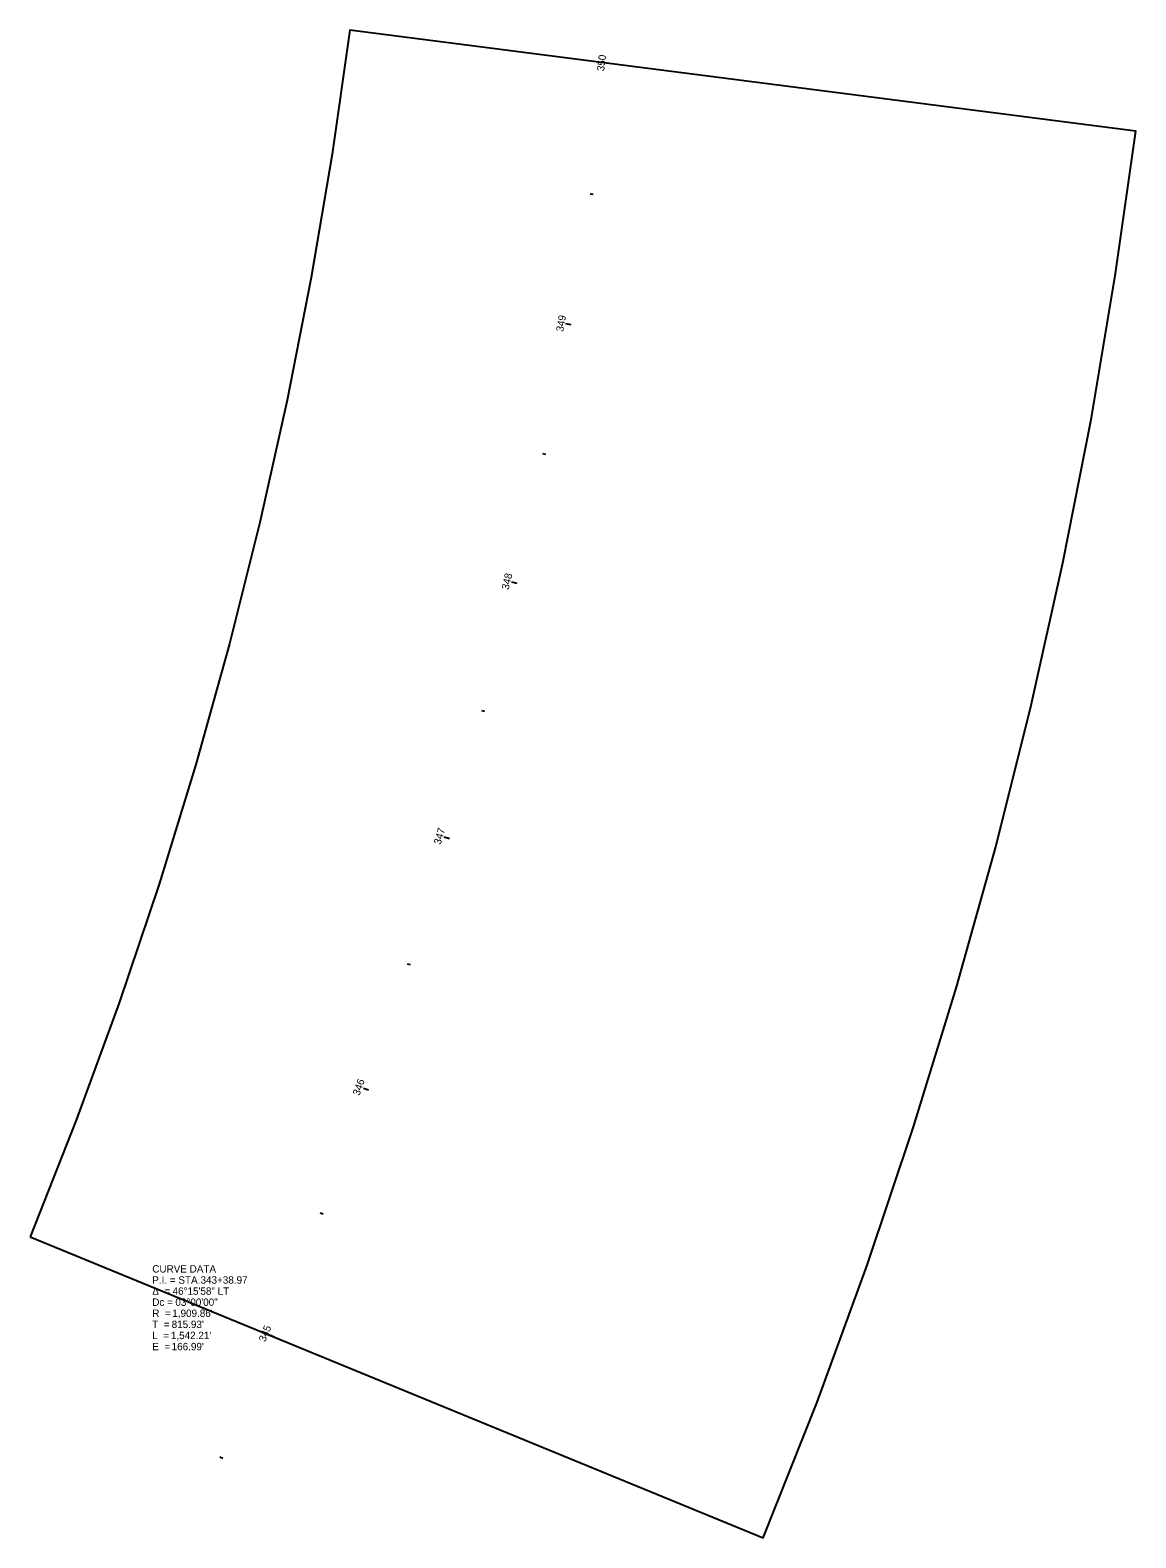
# Model space of a CAD drawing. Extents: x 1380777 to 1381940, y 503546 to 507267.
# Drawn here: x 1381522 to 1381940, y 504407 to 504978 of the extents above; entities that cross this region are included whole.
import ezdxf

# ---------------------------------------------------------------- set-up
doc = ezdxf.new("R2010")
doc.units = 0
for name, color, linetype in [('GE_X_Alignment_1000_Stations', 7, 'Continuous'), ('GE_X_Alignment_100_Curve_Data', 7, 'Continuous'), ('GE_X_Alignment_500_Stations', 7, 'Continuous')]:
    doc.layers.add(name, color=color, linetype=linetype)

msp = doc.modelspace()

# ---------------------------------------------------------------- linework, layer by layer
at = {"layer": 'GE_X_Alignment_1000_Stations'}
msp.add_lwpolyline([(1381521.98, 504521.45), (1381799.48, 504407.46), (1381819.8, 504458.82), (1381838.76, 504510.69), (1381856.36, 504563.05), (1381872.59, 504615.85), (1381887.43, 504669.05), (1381900.87, 504722.63), (1381912.9, 504776.53), (1381923.52, 504830.74), (1381932.71, 504885.2), (1381940.48, 504939.89), (1381642.93, 504978.17), (1381636.27, 504931.26), (1381628.38, 504884.54), (1381619.27, 504838.05), (1381608.95, 504791.8), (1381597.42, 504745.85), (1381584.7, 504700.21), (1381570.78, 504654.92), (1381555.68, 504610.01), (1381539.41, 504565.51)], close=True, dxfattribs=at)
at = {"layer": 'GE_X_Alignment_500_Stations'}
for p, q in [((1381742.11, 504965.41), (1381740.13, 504965.67)), ((1381735.08, 504915.91), (1381733.9, 504916.09)), ((1381726.76, 504866.61), (1381724.79, 504866.97)), ((1381717.15, 504817.54), (1381715.97, 504817.79)), ((1381706.26, 504768.75), (1381704.31, 504769.21)), ((1381694.09, 504720.25), (1381692.93, 504720.56)), ((1381680.66, 504672.09), (1381678.74, 504672.65)), ((1381665.97, 504624.3), (1381664.83, 504624.66)), ((1381650.04, 504576.9), (1381648.15, 504577.57)), ((1381632.87, 504529.94), (1381631.75, 504530.37)), ((1381614.48, 504483.45), (1381612.63, 504484.21)), ((1381594.88, 504437.46), (1381593.78, 504437.94))]:
    msp.add_line(p, q, dxfattribs=at)

# ---------------------------------------------------------------- texts
at = {"layer": 'GE_X_Alignment_100_Curve_Data'}
for s, p in [('CURVE DATA', (1381568.2, 504507.87)), ('P.I. = STA. ', (1381568.2, 504503.67)), ('343+38.97', (1381586.47, 504503.67)), ('Δ  = ', (1381568.2, 504499.47)), ('Dc = ', (1381568.2, 504495.27)), ('46°15\'58" LT', (1381575.88, 504499.47)), ('03°00\'00"', (1381576.94, 504495.27)), ('R  = ', (1381568.2, 504491.07)), ("1,909.86'", (1381575.78, 504491.07)), ('T  = ', (1381568.2, 504486.87)), ("815.93'", (1381575.54, 504486.87)), ('L  = ', (1381568.2, 504482.67)), ('E  = ', (1381568.2, 504478.47)), ("1,542.21'", (1381575.24, 504482.67)), ("166.99'", (1381575.54, 504478.47))]:
    msp.add_text(s, height=2.8, dxfattribs=at).set_placement(p)
at = {"layer": 'GE_X_Alignment_500_Stations'}
for s, rotation, p in [('350', 82.6677, (1381739.21, 504962.49)), ('349', 79.6677, (1381723.72, 504863.88)), ('348', 76.6677, (1381703.07, 504766.16)), ('347', 73.6677, (1381677.35, 504669.68)), ('346', 70.6677, (1381646.6, 504574.66)), ('345', 67.6677, (1381610.95, 504481.43))]:
    msp.add_text(s, height=2.8, rotation=rotation, dxfattribs=at).set_placement(p)

doc.saveas('drawing.dxf')
